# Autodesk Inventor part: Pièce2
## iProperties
Shininess: 64.0
Length Units: 11269
Angle Units: 11279
Time Units: 11290
Mass Units: 11283
Length Display Precision: 3
Angle Display Precision: 2
Compacted: True
Part Number: Pièce2
Document SubType Name: Modeling
Created: 2004-06
Material: Par défaut
Designer: administrateur
Density: 0.0
Volumn: 0.0
Area: 0.0
PropertySet Name: Model Information
Control State: 0
Master: False
Checked Out: False
Author: administrateur
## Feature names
1. Extrusion1
2. Extrusion2
3. Extrusion3
4. Balayage1
5. Réseau rectangulaire1 [Rectangular Pattern]
